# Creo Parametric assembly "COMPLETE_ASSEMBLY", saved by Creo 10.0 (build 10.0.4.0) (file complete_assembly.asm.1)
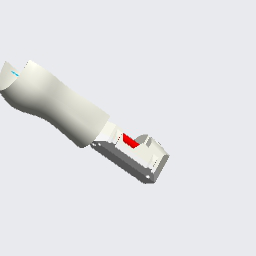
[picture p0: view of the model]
Units: millimeter Kilogram Sec (mmKs); MM, KILOGRAM, SECS

Created from: XX_MMKS_ASM_DESIGN_ABS.ASM

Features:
  1. datum plane "ASM_RIGHT"
  2. datum plane "ASM_TOP"
  3. datum plane "ASM_FRONT"
  4. coordinate system
  5. component "SEMI_COMPLETE_ASSEMBLY"
  6. component "TOP_COVER"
